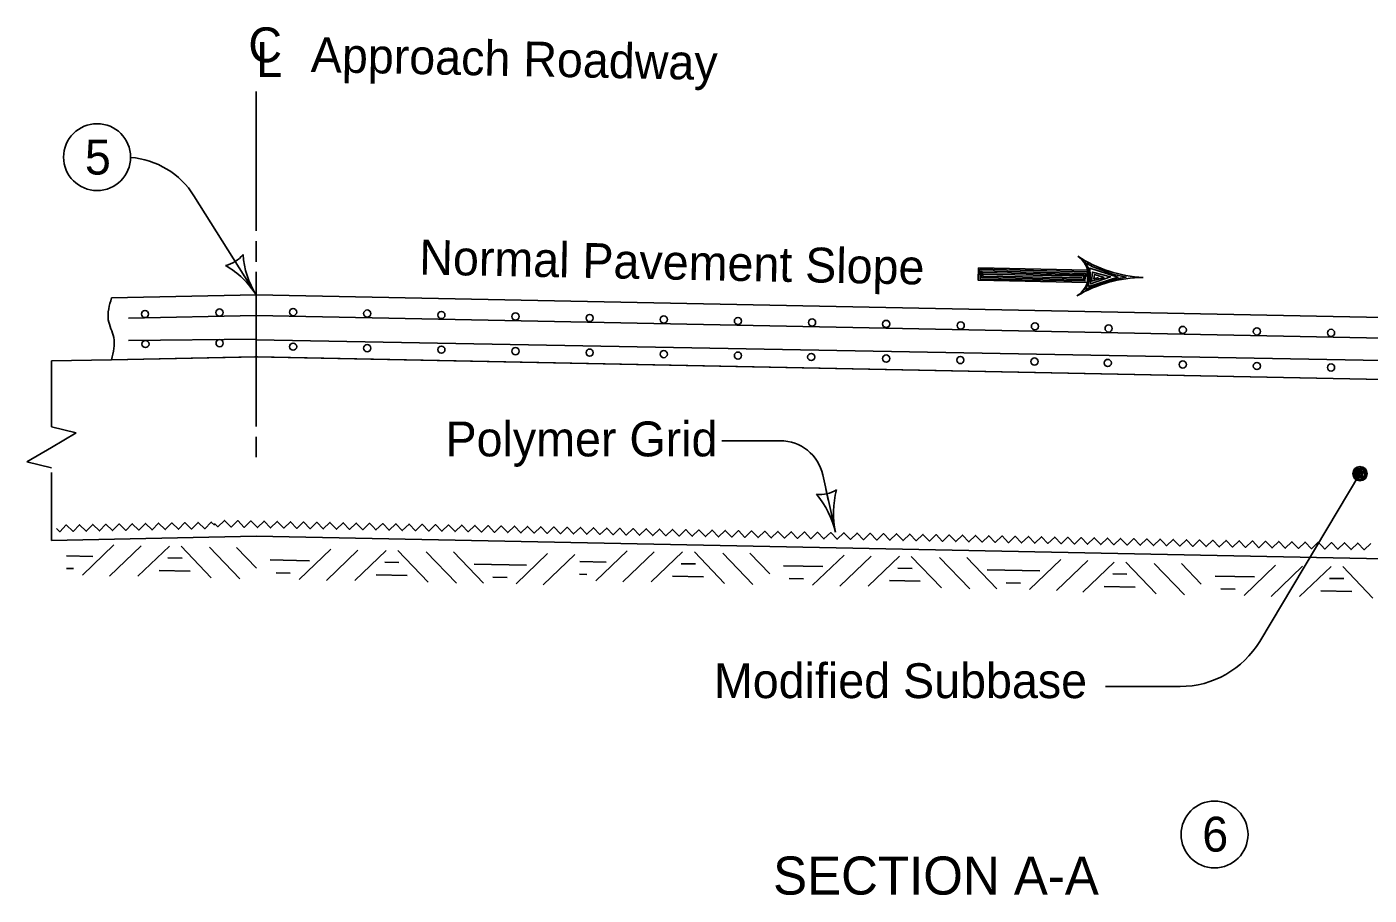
# Model space of a CAD drawing. Extents: x -2135039 to -2124495, y -2139046 to -2132546.
# Drawn here: x -2127595 to -2126979, y -2137598 to -2137199 of the extents above; entities that cross this region are included whole.
import ezdxf

# ---------------------------------------------------------------- set-up
doc = ezdxf.new("R2010")
doc.units = 0
doc.layers.add('BridgeSuperStructureExisting', color=7, linetype='Continuous')
doc.layers.add('dsnStdLabel', color=7, linetype='Continuous')

msp = doc.modelspace()

# ---------------------------------------------------------------- linework, layer by layer
at = {"layer": 'BridgeSuperStructureExisting'}
for p, q in [((-2127518.29, -2137276.76), (-2127489.73, -2137322.31)), ((-2127108.15, -2137310.7), (-2127108.15, -2137310.7)), ((-2127108.06, -2137313.73), (-2127158.19, -2137312.72)), ((-2127108.21, -2137316.56), (-2127108.21, -2137316.56)), ((-2127489.73, -2137322.31), (-2127556.11, -2137323.65)), ((-2127489.73, -2137322.31), (-2127556.11, -2137323.65)), ((-2126779.48, -2137336.57), (-2127489.73, -2137322.31)), ((-2127489.73, -2137322.31), (-2126779.48, -2137336.57)), ((-2127489.77, -2137331.8), (-2127548.28, -2137332.97)), ((-2127489.77, -2137331.8), (-2126758.11, -2137346.48)), ((-2127030.29, -2137340.9), (-2127030.29, -2137340.9)), ((-2126996.26, -2137341.59), (-2126996.26, -2137341.59)), ((-2127489.77, -2137342.63), (-2127548.29, -2137343.26)), ((-2127472.96, -2137344.4), (-2127472.96, -2137344.4)), ((-2127438.92, -2137345.08), (-2127438.92, -2137345.08)), ((-2127404.89, -2137345.76), (-2127404.89, -2137345.76)), ((-2127370.86, -2137346.45), (-2127370.86, -2137346.45)), ((-2127302.79, -2137347.81), (-2127302.79, -2137347.81)), ((-2127556.11, -2137352.01), (-2127583.67, -2137352.56)), ((-2127583.67, -2137352.56), (-2127583.67, -2137382.82)), ((-2127489.16, -2137350.67), (-2127556.11, -2137352.01)), ((-2127556.11, -2137352.01), (-2127490.3, -2137350.69)), ((-2127490.3, -2137350.67), (-2127489.73, -2137350.68)), ((-2127490.3, -2137350.67), (-2126741.2, -2137365.7)), ((-2127489.73, -2137350.68), (-2127489.16, -2137350.67)), ((-2127489.16, -2137350.69), (-2126741.2, -2137365.7)), ((-2127268.76, -2137348.5), (-2127268.76, -2137348.5)), ((-2127234.73, -2137349.18), (-2127234.73, -2137349.18)), ((-2127200.7, -2137349.86), (-2127200.7, -2137349.86)), ((-2127166.66, -2137350.55), (-2127166.66, -2137350.55)), ((-2127132.63, -2137351.23), (-2127132.63, -2137351.23)), ((-2127098.6, -2137351.91), (-2127098.6, -2137351.91)), ((-2127064.57, -2137352.59), (-2127064.57, -2137352.59)), ((-2127030.53, -2137353.28), (-2127030.53, -2137353.28)), ((-2126996.5, -2137353.96), (-2126996.5, -2137353.96)), ((-2127583.67, -2137382.82), (-2127572.33, -2137385.66)), ((-2127572.33, -2137385.66), (-2127583.67, -2137392.27)), ((-2127276.01, -2137389.2), (-2127249.2, -2137389.2)), ((-2127583.67, -2137392.27), (-2127595.02, -2137398.89)), ((-2127595.02, -2137398.89), (-2127583.67, -2137401.73)), ((-2127583.67, -2137403.73), (-2127583.67, -2137434.99)), ((-2127229.67, -2137404.9), (-2127223.86, -2137431.27)), ((-2127029.08, -2137481.32), (-2126983.06, -2137404.35)), ((-2127228.25, -2137411.35), (-2127227.12, -2137416.46)), ((-2127489.73, -2137433.1), (-2127583.67, -2137434.99)), ((-2127489.73, -2137433.1), (-2126673.14, -2137449.49)), ((-2127555.04, -2137437.05), (-2127569.47, -2137450.9)), ((-2127542.6, -2137437.52), (-2127557.02, -2137451.38)), ((-2127529.59, -2137437.56), (-2127544.01, -2137451.41)), ((-2127524.18, -2137437.67), (-2127510.33, -2137452.09)), ((-2127511.18, -2137438.15), (-2127497.32, -2137452.58)), ((-2127498.73, -2137438.18), (-2127489.63, -2137447.65)), ((-2127455.51, -2137439.05), (-2127469.94, -2137452.9)), ((-2127443.07, -2137439.52), (-2127457.49, -2137453.38)), ((-2127430.06, -2137439.56), (-2127444.48, -2137453.41)), ((-2127424.65, -2137439.67), (-2127410.79, -2137454.09)), ((-2127411.65, -2137440.15), (-2127397.79, -2137454.58)), ((-2127399.2, -2137440.18), (-2127385.34, -2137454.6)), ((-2127319.44, -2137439.69), (-2127333.87, -2137453.54)), ((-2127307, -2137440.16), (-2127321.42, -2137454.02)), ((-2127293.99, -2137440.2), (-2127308.41, -2137454.05)), ((-2127355.98, -2137441.04), (-2127370.4, -2137454.9)), ((-2127343.54, -2137441.52), (-2127357.96, -2137455.37)), ((-2127288.58, -2137440.3), (-2127274.72, -2137454.73)), ((-2127275.58, -2137440.79), (-2127261.72, -2137455.21)), ((-2127263.13, -2137440.82), (-2127254.03, -2137450.29)), ((-2127219.91, -2137441.68), (-2127234.33, -2137455.54)), ((-2127207.47, -2137442.16), (-2127221.89, -2137456.01)), ((-2127194.46, -2137442.19), (-2127208.88, -2137456.05)), ((-2127189.05, -2137442.3), (-2127175.19, -2137456.73)), ((-2127176.05, -2137442.79), (-2127162.19, -2137457.21)), ((-2127163.59, -2137442.81), (-2127149.74, -2137457.24)), ((-2127120.38, -2137443.68), (-2127134.8, -2137457.54)), ((-2127107.94, -2137444.16), (-2127122.36, -2137458.01)), ((-2127095.89, -2137444.91), (-2127110.31, -2137458.77)), ((-2127090.48, -2137445.02), (-2127076.62, -2137459.44)), ((-2127077.48, -2137445.51), (-2127063.62, -2137459.93)), ((-2127065.02, -2137445.53), (-2127055.92, -2137455.01)), ((-2127021.81, -2137446.4), (-2127036.23, -2137460.26)), ((-2127009.37, -2137446.88), (-2127023.79, -2137460.73)), ((-2126996.36, -2137446.91), (-2127010.78, -2137460.77)), ((-2126990.95, -2137447.02), (-2126977.09, -2137461.44)), ((-2127099.87, -2137502.03), (-2127065.59, -2137502.03))]:
    msp.add_line(p, q, dxfattribs=at)
for points in [[(-2127489.73, -2137228.89), (-2127489.73, -2137292.85)], [(-2127489.73, -2137297.58), (-2127489.73, -2137307.04)], [(-2127108.09, -2137310.89), (-2127158.13, -2137309.88), (-2127158.25, -2137315.55), (-2127108.21, -2137316.56), (-2127108.27, -2137311.7), (-2127157.5, -2137310.52), (-2127157.47, -2137315.04), (-2127109.3, -2137315.82), (-2127109.1, -2137312.44), (-2127156.83, -2137311.29), (-2127156.76, -2137314.3), (-2127109.91, -2137315.24), (-2127109.74, -2137313.12), (-2127156.27, -2137311.93), (-2127156.25, -2137313.62), (-2127110.52, -2137314.48)], [(-2127109.37, -2137307.17), (-2127107.31, -2137310.59), (-2127107.16, -2137315.55), (-2127109.06, -2137319.83), (-2127101.61, -2137316.91), (-2127092.92, -2137314.58), (-2127090.46, -2137314.06), (-2127096.7, -2137312.69), (-2127105.72, -2137309.37), (-2127108.38, -2137307.88), (-2127107.59, -2137318.42), (-2127094.16, -2137314.18), (-2127107.11, -2137309.97), (-2127106.76, -2137317.25), (-2127097.55, -2137314.05), (-2127105.89, -2137311.81), (-2127106.35, -2137316), (-2127100.49, -2137314.24), (-2127104.91, -2137312.9), (-2127105.2, -2137314.9), (-2127103.06, -2137314.31)], [(-2127489.73, -2137311.76), (-2127489.73, -2137382.66)], [(-2127490.3, -2137350.69), (-2127490.3, -2137350.67)], [(-2127489.16, -2137350.67), (-2127489.16, -2137350.69)], [(-2127489.73, -2137387.38), (-2127489.73, -2137396.84)], [(-2126983.32, -2137407.39), (-2126982.2, -2137406.89), (-2126980.47, -2137406.35), (-2126980.13, -2137404.59), (-2126980.37, -2137403.04), (-2126981.48, -2137401.61), (-2126983.13, -2137401.76), (-2126984.88, -2137402), (-2126985.72, -2137403.39), (-2126985.86, -2137404.85), (-2126984.84, -2137406.77), (-2126983.56, -2137406.93), (-2126981.83, -2137406.49), (-2126980.4, -2137405.38), (-2126980.45, -2137403.72), (-2126981.56, -2137402.4), (-2126983.12, -2137402.25), (-2126984.86, -2137402.59), (-2126985.13, -2137403.57), (-2126985.48, -2137404.74), (-2126984.66, -2137406.18), (-2126983.39, -2137406.15), (-2126981.94, -2137405.91), (-2126980.9, -2137405.1), (-2126981.42, -2137403.65), (-2126982.52, -2137402.81), (-2126983.98, -2137402.75), (-2126984.35, -2137403.55), (-2126984.81, -2137404.43), (-2126984.09, -2137405.58), (-2126983.01, -2137405.84), (-2126982.06, -2137405.33), (-2126981.99, -2137404.26), (-2126982.5, -2137403.49), (-2126983.48, -2137403.22), (-2126983.95, -2137403.63), (-2126984.23, -2137404.22), (-2126983.72, -2137405.08), (-2126983.03, -2137405.26), (-2126982.36, -2137404.85), (-2126982.47, -2137404.27), (-2126982.97, -2137403.89), (-2126983.65, -2137403.91), (-2126983.64, -2137404.4), (-2126983.05, -2137404.67)], [(-2127581.4, -2137429.51), (-2127579.86, -2137430.99), (-2127576.9, -2137427.9), (-2127573.81, -2137430.87), (-2127570.85, -2137427.78), (-2127567.77, -2137430.74), (-2127564.8, -2137427.66), (-2127561.72, -2137430.62), (-2127558.75, -2137427.54), (-2127555.67, -2137430.5), (-2127552.7, -2137427.42), (-2127549.62, -2137430.38), (-2127546.66, -2137427.3), (-2127543.57, -2137430.26), (-2127540.61, -2137427.17), (-2127537.53, -2137430.14), (-2127534.56, -2137427.05), (-2127531.47, -2137430.02), (-2127528.51, -2137426.93), (-2127525.42, -2137429.89), (-2127522.46, -2137426.81), (-2127519.38, -2137429.77), (-2127516.42, -2137426.69), (-2127513.33, -2137429.65), (-2127510.36, -2137426.57), (-2127508.82, -2137428.05)], [(-2127508.82, -2137427.19), (-2127507.34, -2137428.73), (-2127504.25, -2137425.77), (-2127501.29, -2137428.86), (-2127498.2, -2137425.9), (-2127495.24, -2137428.98), (-2127492.16, -2137426.02), (-2127489.2, -2137429.1), (-2127486.11, -2137426.13), (-2127483.14, -2137429.22), (-2127480.06, -2137426.26), (-2127477.09, -2137429.34), (-2127474.01, -2137426.38), (-2127471.05, -2137429.47), (-2127467.96, -2137426.5), (-2127465, -2137429.59), (-2127461.92, -2137426.62), (-2127458.95, -2137429.7), (-2127455.86, -2137426.74), (-2127452.9, -2137429.83), (-2127449.81, -2137426.87), (-2127446.85, -2137429.95), (-2127443.77, -2137426.99), (-2127440.81, -2137430.07), (-2127437.72, -2137427.1), (-2127436.23, -2137428.65)], [(-2127436.23, -2137428.65), (-2127434.75, -2137430.19), (-2127431.67, -2137427.23), (-2127428.7, -2137430.31), (-2127425.62, -2137427.35), (-2127422.66, -2137430.44), (-2127419.57, -2137427.47), (-2127416.61, -2137430.56), (-2127413.53, -2137427.59), (-2127410.56, -2137430.68), (-2127407.48, -2137427.71), (-2127404.51, -2137430.8), (-2127401.43, -2137427.84), (-2127398.46, -2137430.92), (-2127395.38, -2137427.96), (-2127392.41, -2137431.04), (-2127389.33, -2137428.08), (-2127386.37, -2137431.16), (-2127383.28, -2137428.2), (-2127380.32, -2137431.28), (-2127377.23, -2137428.32), (-2127374.26, -2137431.41), (-2127371.18, -2137428.44), (-2127368.22, -2137431.53), (-2127365.13, -2137428.56), (-2127363.65, -2137430.11)], [(-2127363.65, -2137430.11), (-2127362.17, -2137431.65), (-2127359.09, -2137428.69), (-2127356.12, -2137431.77), (-2127353.04, -2137428.81), (-2127350.07, -2137431.89), (-2127346.98, -2137428.93), (-2127344.02, -2137432.01), (-2127340.94, -2137429.05), (-2127337.98, -2137432.13), (-2127334.89, -2137429.17), (-2127331.93, -2137432.26), (-2127328.84, -2137429.29), (-2127325.87, -2137432.38), (-2127322.79, -2137429.41), (-2127319.83, -2137432.5), (-2127316.74, -2137429.53), (-2127313.78, -2137432.62), (-2127310.7, -2137429.66), (-2127307.73, -2137432.74), (-2127304.65, -2137429.78), (-2127301.68, -2137432.86), (-2127298.6, -2137429.9), (-2127295.63, -2137432.98), (-2127292.55, -2137430.02), (-2127291.07, -2137431.56)], [(-2127291.07, -2137431.56), (-2127289.59, -2137433.1), (-2127286.5, -2137430.14), (-2127283.54, -2137433.23), (-2127280.45, -2137430.26), (-2127277.49, -2137433.35), (-2127274.4, -2137430.38), (-2127271.44, -2137433.47), (-2127268.35, -2137430.5), (-2127265.39, -2137433.59), (-2127262.31, -2137430.63), (-2127259.34, -2137433.71), (-2127256.26, -2137430.75), (-2127253.29, -2137433.84), (-2127250.21, -2137430.87), (-2127247.24, -2137433.95), (-2127244.16, -2137430.99), (-2127241.2, -2137434.07), (-2127238.11, -2137431.11), (-2127235.15, -2137434.2), (-2127232.06, -2137431.24), (-2127229.1, -2137434.32), (-2127226.01, -2137431.36), (-2127223.05, -2137434.44), (-2127219.96, -2137431.48), (-2127218.48, -2137433.02)], [(-2127218.48, -2137433.02), (-2127217, -2137434.56), (-2127213.92, -2137431.6), (-2127210.95, -2137434.68), (-2127207.87, -2137431.72), (-2127204.9, -2137434.81), (-2127201.82, -2137431.84), (-2127198.85, -2137434.93), (-2127195.77, -2137431.96), (-2127192.81, -2137435.05), (-2127189.72, -2137432.08), (-2127186.76, -2137435.17), (-2127183.67, -2137432.21), (-2127180.71, -2137435.29), (-2127177.62, -2137432.33), (-2127174.66, -2137435.41), (-2127171.57, -2137432.45), (-2127168.61, -2137435.53), (-2127165.52, -2137432.57), (-2127162.56, -2137435.65), (-2127159.48, -2137432.69), (-2127156.51, -2137435.78), (-2127153.43, -2137432.81), (-2127150.46, -2137435.9), (-2127147.38, -2137432.93), (-2127145.9, -2137434.48)], [(-2127145.9, -2137434.48), (-2127144.41, -2137436.02), (-2127141.33, -2137433.05), (-2127138.37, -2137436.14), (-2127135.28, -2137433.18), (-2127132.32, -2137436.26), (-2127129.23, -2137433.3), (-2127126.27, -2137436.38), (-2127123.18, -2137433.42), (-2127120.22, -2137436.5), (-2127117.13, -2137433.54), (-2127114.17, -2137436.63), (-2127111.09, -2137433.66), (-2127108.12, -2137436.75), (-2127105.04, -2137433.78), (-2127102.07, -2137436.87), (-2127098.99, -2137433.9), (-2127096.02, -2137436.99), (-2127092.94, -2137434.03), (-2127089.98, -2137437.11), (-2127086.89, -2137434.15), (-2127083.93, -2137437.23), (-2127080.84, -2137434.27), (-2127077.88, -2137437.35), (-2127074.79, -2137434.39), (-2127073.31, -2137435.93)], [(-2127073.31, -2137435.93), (-2127071.83, -2137437.47), (-2127068.75, -2137434.51), (-2127065.78, -2137437.6), (-2127062.7, -2137434.64), (-2127059.73, -2137437.72), (-2127056.65, -2137434.75), (-2127053.68, -2137437.84), (-2127050.6, -2137434.87), (-2127047.64, -2137437.96), (-2127044.55, -2137435), (-2127041.59, -2137438.08), (-2127038.5, -2137435.12), (-2127035.54, -2137438.21), (-2127032.45, -2137435.24), (-2127029.49, -2137438.32), (-2127026.4, -2137435.36), (-2127023.44, -2137438.44), (-2127020.36, -2137435.48), (-2127017.39, -2137438.57), (-2127014.31, -2137435.61), (-2127011.34, -2137438.69), (-2127008.26, -2137435.73), (-2127005.29, -2137438.81), (-2127002.21, -2137435.84), (-2127000.73, -2137437.39)], [(-2127000.73, -2137437.39), (-2126999.25, -2137438.93), (-2126996.16, -2137435.97), (-2126993.2, -2137439.05), (-2126990.12, -2137436.09), (-2126987.15, -2137439.18), (-2126984.06, -2137436.21), (-2126981.1, -2137439.3), (-2126978.01, -2137436.33)], [(-2127576.76, -2137442.09), (-2127564.73, -2137442.33)], [(-2127530.26, -2137443.04), (-2127523.73, -2137443.18)], [(-2127483.26, -2137443.96), (-2127465.2, -2137444.33)], [(-2127430.73, -2137445.04), (-2127424.2, -2137445.17)], [(-2127389.73, -2137445.84), (-2127365.67, -2137446.33)], [(-2127341.16, -2137444.73), (-2127329.13, -2137444.97)], [(-2127294.66, -2137445.68), (-2127288.13, -2137445.81)], [(-2127576.88, -2137447.89), (-2127573.61, -2137447.95)], [(-2127534.21, -2137448.82), (-2127520.02, -2137449.11)], [(-2127480.61, -2137449.82), (-2127474.08, -2137449.95)], [(-2127434.68, -2137450.82), (-2127420.49, -2137451.11)], [(-2127381.08, -2137451.82), (-2127374.55, -2137451.95)], [(-2127341.28, -2137450.52), (-2127338.01, -2137450.59)], [(-2127298.61, -2137451.46), (-2127284.42, -2137451.74)], [(-2127247.66, -2137446.6), (-2127229.6, -2137446.96)], [(-2127245.01, -2137452.46), (-2127238.48, -2137452.59)], [(-2127195.13, -2137447.68), (-2127188.6, -2137447.81)], [(-2127154.12, -2137448.48), (-2127130.07, -2137448.96)], [(-2127096.56, -2137450.4), (-2127090.03, -2137450.53)], [(-2127049.56, -2137451.32), (-2127031.5, -2137451.68)], [(-2126997.03, -2137452.4), (-2126990.49, -2137452.53)], [(-2127199.08, -2137453.46), (-2127184.89, -2137453.74)], [(-2127145.48, -2137454.45), (-2127138.95, -2137454.58)], [(-2127100.51, -2137456.18), (-2127086.32, -2137456.46)], [(-2127046.91, -2137457.17), (-2127040.38, -2137457.3)], [(-2127000.97, -2137458.17), (-2126986.78, -2137458.46)]]:
    msp.add_lwpolyline(points, dxfattribs=at)
for centre, radius in [((-2127562.78, -2137259.03), 15.36), ((-2127506.58, -2137330.38), 1.65), ((-2127472.8, -2137330.16), 1.65), ((-2127438.77, -2137330.84), 1.65), ((-2127540.77, -2137331.07), 1.65), ((-2127404.74, -2137331.53), 1.65), ((-2127370.7, -2137332.21), 1.65), ((-2127336.67, -2137332.89), 1.65), ((-2127302.64, -2137333.57), 1.65), ((-2127268.6, -2137334.26), 1.65), ((-2127234.57, -2137334.94), 1.65), ((-2127200.54, -2137335.62), 1.65), ((-2127166.34, -2137336.32), 1.65), ((-2127132.26, -2137336.71), 1.65), ((-2127098.44, -2137337.67), 1.65), ((-2127064.41, -2137338.36), 1.65), ((-2127030.37, -2137339.04), 1.65), ((-2126996.34, -2137339.72), 1.65), ((-2127540.57, -2137344.82), 1.65), ((-2127506.53, -2137344.45), 1.65), ((-2127472.8, -2137346.04), 1.65), ((-2127438.77, -2137346.73), 1.65), ((-2127404.73, -2137347.41), 1.65), ((-2127370.7, -2137348.09), 1.65), ((-2127336.67, -2137348.78), 1.65), ((-2127302.64, -2137349.46), 1.65), ((-2127268.6, -2137350.14), 1.65), ((-2127234.96, -2137350.79), 1.65), ((-2127200.54, -2137351.51), 1.65), ((-2127166.51, -2137352.19), 1.65), ((-2127132.47, -2137352.88), 1.65), ((-2127098.83, -2137353.52), 1.65), ((-2127064.41, -2137354.24), 1.65), ((-2127030.38, -2137354.92), 1.65), ((-2126996.35, -2137355.6), 1.65), ((-2126983.06, -2137404.35), 3.31), ((-2127049.82, -2137569.97), 15.36)]:
    msp.add_circle(centre, radius, dxfattribs=at)
for centre, radius, start, end in [((-2127550.33, -2137296.85), 37.81, 32.09002, 85.59039), ((-2127507.62, -2137293.77), 15.52, 284.35693, 319.82363), ((-2127507.62, -2137293.77), 15.52, 284.35693, 319.82363), ((-2127455.69, -2137300.97), 40.18, 184.01779, 212.09028), ((-2127455.69, -2137300.97), 40.18, 184.01779, 212.09028), ((-2127118.43, -2137313.52), 10.67, 300.56474, 57.13538), ((-2127079.57, -2137253.36), 60.95, 237.1358, 267.16583), ((-2127523.77, -2137343.66), 40.18, 32.09028, 60.16277), ((-2127523.77, -2137343.66), 40.18, 32.09028, 60.16277), ((-2127082.01, -2137375.19), 60.95, 90.53429, 120.56432), ((-2127249.2, -2137409.2), 20, 12.43142, 90), ((-2127231.1, -2137398.37), 15.52, 264.68499, 300.15169), ((-2127263.09, -2137439.91), 40.18, 12.41834, 40.49083), ((-2127184.62, -2137422.63), 40.18, 164.34585, 192.41834), ((-2127065.59, -2137459.49), 42.54, 270, 329.12488)]:
    msp.add_arc(centre, radius, start, end, dxfattribs=at)
msp.add_spline([(-2127556.11, -2137323.65), (-2127557.62, -2137333.73), (-2127555.16, -2137341.86), (-2127556.11, -2137352.01)], degree=3, dxfattribs=at)
msp.add_spline([(-2127556.11, -2137323.65), (-2127557.62, -2137333.73), (-2127555.16, -2137341.86), (-2127556.11, -2137352.01)], degree=3, dxfattribs=at)
at = {"layer": 'dsnStdLabel'}
msp.add_line((-2126758.22, -2137356.41), (-2127489.77, -2137342.86), dxfattribs=at)

# ---------------------------------------------------------------- texts
at = {"layer": 'BridgeSuperStructureExisting'}
msp.add_text('SECTION A-A', height=17.5, dxfattribs=at).set_placement((-2127252.46, -2137597.59))
at = {"layer": 'dsnStdLabel'}
for s, p in [('C', (-2127493.34, -2137215.46)), ('L', (-2127489.74, -2137222.17)), ('5', (-2127568.36, -2137267.03)), ('Polymer Grid', (-2127402.83, -2137396.4)), ('Modified Subbase', (-2127279.62, -2137507.38)), ('6', (-2127055.45, -2137577.84))]:
    msp.add_text(s, height=16, dxfattribs=at).set_placement(p)
for s, p in [('Approach Roadway', (-2127464.78, -2137219.93)), ('Normal Pavement Slope', (-2127414.99, -2137312.89))]:
    msp.add_text(s, height=16, rotation=358.85018, dxfattribs=at).set_placement(p)

doc.saveas('drawing.dxf')
